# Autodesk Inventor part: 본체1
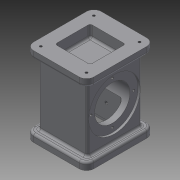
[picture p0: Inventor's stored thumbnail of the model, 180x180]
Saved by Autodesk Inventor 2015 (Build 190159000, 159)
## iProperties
Created: 2017-08
Part Number: 본체1
Material: 일반
Document SubType Name: Modeling
Designer: owner
Density: 1 g/cm^3
Appearance: 기본값
Author: owner
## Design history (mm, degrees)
sketch "스케치1"
  geometry: L1 (33, -37)-(-33, -37); L2 (-33, -37)-(-33, 37); L3 (-33, 37)-(33, 37); L4 (33, 37)-(33, -37); L5 (33, -37)-(-33, 37); L6 (-33, -37)-(33, 37); 1 further point
  constraints: 12 end point, 2 midpoint, 2 parallel, 1 horizontal, 1 perpendicular
  dimensions: "d0" = 66 distance of L2.end L3.end; "d1" = 74 distance of L3.end L1.start
extrude "돌출1" new body sketch "스케치1" stored distance "d2" = 108; taper "d3" = 0 deg
sketch "스케치2"
  geometry: L1 (-26, 26)-(26, 26); L2 (26, 26)-(26, -26); L3 (26, -26)-(-26, -26); L4 (-26, -26)-(-26, 26); L5 (-26, 26)-(26, -26); L6 (26, 26)-(-26, -26); 1 further point
  constraints: 12 end point, 2 midpoint, 2 parallel, 1 horizontal, 1 perpendicular
  dimensions: "d4" = 52 distance of L2.end L3.end; "d5" = 52 distance of L3.end L1.start
extrude "돌출2" cut sketch "스케치2" distance "d6" = 8; taper "d7" = 0 deg
sketch "스케치4"
  geometry: L1 (24, 24)-(-24, 24); L2 (-24, 24)-(-24, -24); L3 (-24, -24)-(24, -24); L4 (24, -24)-(24, 24); L5 (24, 24)-(-24, -24); L6 (-24, 24)-(24, -24); 1 further point
  constraints: 12 end point, 2 midpoint, 2 parallel, 1 horizontal, 1 perpendicular
  dimensions: "d11" = 48 distance of L1.end L2.end; "d12" = 48 distance of L1.start L1.end
extrude "돌출4" cut sketch "스케치4" distance "d13" = 16; taper "d14" = 0 deg
sketch "스케치5"
  geometry: L1 (-33, -37)-(33, -37) reference; L2 (33, -37)-(33, 37) reference; L3 (33, 37)-(-33, 37) reference; L4 (-33, 37)-(-33, -37) reference; L5 (41, 46)-(-41, 46); L6 (-41, 46)-(-41, -46); L7 (-41, -46)-(41, -46); L8 (41, -46)-(41, 46); L9 (41, 46)-(-41, -46); L10 (-41, 46)-(41, -46); 1 further point
  constraints: 12 end point, 2 midpoint, 2 parallel, 1 horizontal, 1 perpendicular
  dimensions: "d15" = 92 distance of L5.end L6.end; "d16" = 82 distance of L5.start L5.end
extrude "돌출5" join sketch "스케치5" distance "d17" = 10; taper "d18" = 0 deg
sketch "스케치6"
  geometry: C1 r 35 at (54, 37); 1 further point
  constraints: 1 centre point, 1 coincident
  dimensions: "d19" = 70 diameter of C1
extrude "돌출6" cut sketch "스케치6" distance "d20" = 3; taper "d21" = 0 deg
hole "구멍1" diameter "d24" = 48; stored, may be unused: countersink angle "d28" = 90 deg, drill point angle "d30" = 0 deg; dims "d22" = 10, "d23" = 10, "d25" = 6, "d26" = 4, "d27" = 2, "d29" = 8
sketch "스케치7"
  geometry: L1 (-22, 22)-(22, 22); L2 (22, 22)-(22, -22); L3 (22, -22)-(-22, -22); L4 (-22, -22)-(-22, 22); L5 (-22, 22)-(22, -22); L6 (22, 22)-(-22, -22); 1 further point
  constraints: 12 end point, 2 midpoint, 2 parallel, 1 horizontal, 1 perpendicular
  dimensions: "d31" = 44 distance of L1.end L2.end; "d32" = 44 distance of L2.end L3.end
extrude "돌출7" cut sketch "스케치7" distance "d33" = 74; taper "d34" = 0 deg
sketch "스케치8"
  geometry: L1 (-41, 46)-(41, 46); L2 (41, 46)-(41, -46); L3 (41, -46)-(-41, -46); L4 (-41, -46)-(-41, 46); L5 (-41, 46)-(41, -46); L6 (41, 46)-(-41, -46); L7 (-33, -37)-(33, -37) reference; L8 (-33, 37)-(-33, -37) reference; L9 (33, 37)-(-33, 37) reference; L10 (33, -37)-(33, 37) reference; 1 further point
  constraints: 12 end point, 2 midpoint, 2 parallel, 1 horizontal, 1 perpendicular
  dimensions: "d35" = 82 distance of L2.end L3.end; "d36" = 92 distance of L3.end L1.start
extrude "돌출8" join sketch "스케치8" distance "d37" = 10; taper "d38" = 0 deg
sketch "스케치9"
  geometry: 2 further points
  dimensions: "d39" = 31 horizontal distance of point (31, -36) point (0, 0); "d40" = 36 vertical distance of point (0, 0) point (31, -36)
hole "구멍2" sketch "스케치9" at (31, -36) diameter "d41" = 3.242; stored, may be unused: countersink angle "d45" = 90 deg, drill point angle "d47" = 118 deg; dims "d42" = 4, "d43" = 4, "d44" = 2, "d46" = 6
fillet "모깎기1" dims "d48" = 10
fillet "모깎기2" dims "d49" = 3
sketch "스케치10"
  geometry: L1 (64, -10)-(2, -10) reference; 3 further points
  constraints: 2 vertical alignment
  dimensions: "d51" = 38 distance from line of point (33, 28) L1; "d52" = 42 distance of point (33, 70) point (33, 28)
hole "구멍3" sketch "스케치10" at (33, 70), (33, 28) diameter "d53" = 4.134; stored, may be unused: countersink angle "d57" = 90 deg, drill point angle "d59" = 118 deg; dims "d54" = 10, "d55" = 4, "d56" = 2, "d58" = 27.7
sketch "스케치11"
  geometry: 2 further points
  constraints: 1 horizontal alignment
  dimensions: "d60" = 29 distance of point (0, 0) point (-29, 0)
hole "구멍4" sketch "스케치11" at (-29, 0) diameter "d61" = 3.242; stored, may be unused: countersink angle "d65" = 90 deg, drill point angle "d67" = 118 deg; dims "d62" = 4, "d63" = 4, "d64" = 2, "d66" = 6
fillet "모깎기3" dims "d71" = 3
fillet "모깎기4" dims "d72" = 3
fillet "모깎기6" dims "d74" = 3
fillet "모깎기7" dims "d75" = 3
chamfer "모따기1" distance "d76" = 1; stored, may be unused: second distance "d77" = 2, angle "d78" = 45 deg
sketch "스케치12"
  geometry: L1 (0, -10)-(7, -10) reference; L2 (0, 72)-(0, 0) reference; 2 further points
  constraints: 1 other
  dimensions: "d85" = 46 distance from line of L1 point (4, 36); "d86" = 4 distance from line of point (4, 36) L2
feature "엠보싱1" sketch "스케치12" dims "d0" = 66, "d1" = 74, "d11" = 48, "d12" = 48, "d87" = 0.5, "d88" = 0
fillet "모깎기8" dims "d89" = 3
fillet "모깎기9" dims "d90" = 3
fillet "모깎기10" dims "d91" = 3
node "솔리드1"
mirror "대칭1"
mirror "대칭2"
mirror "대칭3"
mirror "대칭4"
pattern_circular "원형 패턴1" dims angle "d69" = 360 deg
mirror "대칭5"
